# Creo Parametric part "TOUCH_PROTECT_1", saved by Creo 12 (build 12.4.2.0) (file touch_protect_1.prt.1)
Units: Custom; MM, KILOGRAM, SECS

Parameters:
  PTC_WM_ITERATION = "0"
  PTC_WM_VERSION = "-.0"
  PTC_WM_LIFECYCLE_STATE = "In Work"
  PTC_WM_LIFECYCLE = "MO_CADDocument"
  PTC_WM_CREATED_BY = "Maximilian Roepper (Z0017RMS: MO)"
  PTC_WM_CREATED_ON = "18-Sep-26 11:36:42 AM"
  PTC_WM_MODIFIED_BY = "Maximilian Roepper (Z0017RMS: MO)"
  PTC_WM_MODIFIED_ON = "18-Sep-26 11:36:46 AM"
  PDMLINKNUMBER = "PDM000071455339"
  PTC_WM_NAME = "touch_protect_1.prt"
  PTC_WM_NUMBER = "PDM000071455339"

Other parameters: WEIGHT, WEIGHT_FACTOR, WEIGHT_ADD, _MASS_TEMP, _DIFF_TEMP, MC_ERRORS, SUPPLIER

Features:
  1. coordinate system
  2. datum plane "PRT_YZ"
  3. datum plane "PRT_XY"
  4. datum plane "PRT_XZ"
  5. coordinate system
  6. datum axis
  7. datum axis
  8. datum axis
  9. coordinate system
  10. imported feature

Other named items: PRT, SIEMENS_MO, DRW_VIEW_ORG, PRT_X, PRT_Y, PRT_Z, CS0, ROUGH_GROB

Layers: 00_STD_CSYS-KSYS, 01_STD_PLANES-EBENEN, 02_STD_AXES-ACHSEN, 03_STD_CSYS-KSYS, 24_IMPORT_FEAT-IMPORT_KE

Surfaces: 6 plane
